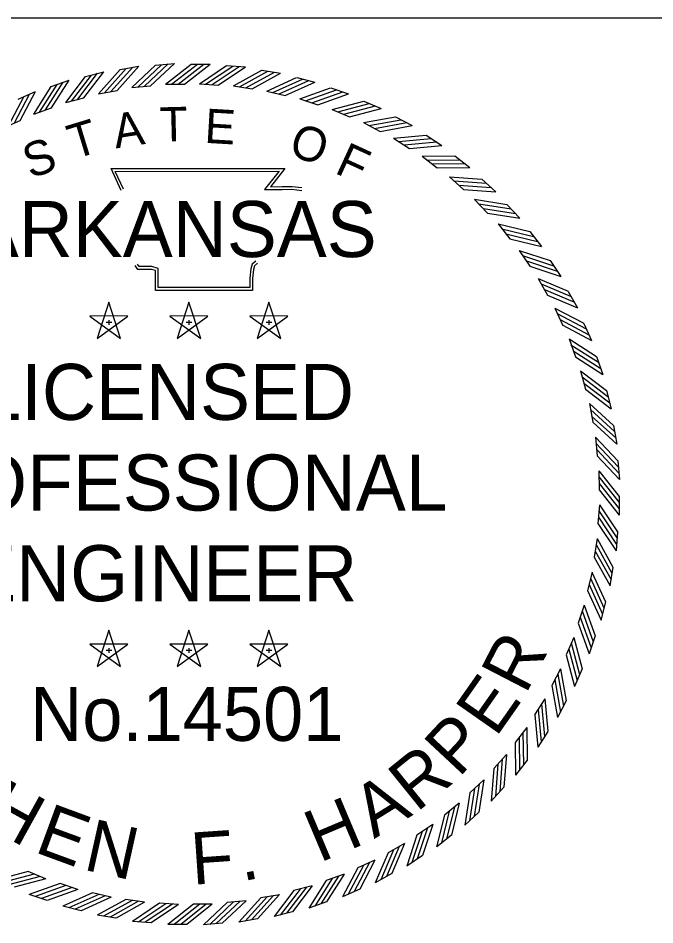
# Model space of a CAD drawing. Extents: x 16 to 1228740, y 11 to 152440.
# Drawn here: x 17.737 to 17.8643, y 10.8174 to 10.9986 of the extents above; entities that cross this region are included whole.
import ezdxf

# ---------------------------------------------------------------- set-up
doc = ezdxf.new("R2010")
doc.units = 0
doc.layers.add('R_No Plot', color=7, linetype='Continuous')
doc.layers.add('STAMP_FRED', color=7, linetype='Continuous')

msp = doc.modelspace()

# ---------------------------------------------------------------- linework, layer by layer
at = {"layer": 'R_No Plot'}
msp.add_line((17.888, 10.99864), (17.47349, 10.99864), dxfattribs=at)
at = {"layer": 'STAMP_FRED'}
for p, q in [((17.75049, 10.98696), (17.75413, 10.98792)), ((17.75745, 10.98838), (17.76116, 10.98904)), ((17.7645, 10.98923), (17.76826, 10.98957)), ((17.77164, 10.98944), (17.77541, 10.98944)), ((17.7787, 10.98916), (17.78246, 10.98888)), ((17.78575, 10.98824), (17.78947, 10.98765)), ((17.74366, 10.98497), (17.74722, 10.98623)), ((17.7927, 10.98675), (17.79636, 10.98586)), ((17.75975, 10.98476), (17.76351, 10.98511)), ((17.7665, 10.98543), (17.77028, 10.98543)), ((17.77328, 10.98553), (17.77705, 10.98526)), ((17.78004, 10.98508), (17.78378, 10.98449)), ((17.7995, 10.98468), (17.80308, 10.98349)), ((17.73703, 10.98242), (17.74047, 10.98397)), ((17.74653, 10.98177), (17.75018, 10.98274)), ((17.75308, 10.98354), (17.7568, 10.9842)), ((17.78675, 10.98407), (17.79042, 10.98317)), ((17.79335, 10.9825), (17.79694, 10.98131)), ((17.74015, 10.97947), (17.74371, 10.98073)), ((17.80611, 10.98207), (17.80957, 10.98058)), ((17.7998, 10.9804), (17.80327, 10.97892)), ((17.81247, 10.97891), (17.81581, 10.97715)), ((17.73398, 10.97665), (17.73743, 10.9782)), ((17.80605, 10.97778), (17.80939, 10.97601)), ((17.81856, 10.97525), (17.82173, 10.97321)), ((17.81206, 10.97464), (17.81525, 10.9726)), ((17.8178, 10.97102), (17.8208, 10.96873)), ((17.82432, 10.97109), (17.82732, 10.9688)), ((17.82321, 10.96694), (17.82602, 10.96441)), ((17.82972, 10.96647), (17.83252, 10.96394)), ((17.82827, 10.96242), (17.83086, 10.95967)), ((17.83472, 10.96142), (17.8373, 10.95867)), ((17.83295, 10.95751), (17.83529, 10.95455)), ((17.83929, 10.95597), (17.84163, 10.95302)), ((17.83719, 10.95222), (17.83929, 10.94908)), ((17.84338, 10.95017), (17.84548, 10.94703)), ((17.84099, 10.9466), (17.84282, 10.9433)), ((17.84699, 10.94404), (17.84882, 10.94074)), ((17.75517, 10.94187), (17.75281, 10.93464)), ((17.75752, 10.93464), (17.75517, 10.94188)), ((17.77116, 10.94187), (17.7688, 10.93464)), ((17.77351, 10.93464), (17.77116, 10.94188)), ((17.78715, 10.94187), (17.78479, 10.93464)), ((17.7895, 10.93464), (17.78715, 10.94188)), ((17.75897, 10.93911), (17.75136, 10.93912)), ((17.75137, 10.93911), (17.75752, 10.93463)), ((17.75282, 10.93464), (17.75898, 10.93911)), ((17.77496, 10.93911), (17.76735, 10.93912)), ((17.76736, 10.93911), (17.77351, 10.93463)), ((17.76881, 10.93464), (17.77497, 10.93911)), ((17.79095, 10.93911), (17.78334, 10.93912)), ((17.78335, 10.93911), (17.7895, 10.93463)), ((17.7848, 10.93464), (17.79096, 10.93911)), ((17.84431, 10.94069), (17.84586, 10.93724)), ((17.75463, 10.9379), (17.75576, 10.9379)), ((17.75518, 10.9383), (17.75518, 10.93735)), ((17.77062, 10.9379), (17.77175, 10.9379)), ((17.77117, 10.9383), (17.77117, 10.93735)), ((17.78661, 10.9379), (17.78774, 10.9379)), ((17.78716, 10.9383), (17.78716, 10.93735)), ((17.85008, 10.93764), (17.85163, 10.9342)), ((17.84713, 10.93452), (17.84839, 10.93096)), ((17.85263, 10.93101), (17.85389, 10.92745)), ((17.84943, 10.92814), (17.85039, 10.92449)), ((17.85462, 10.92419), (17.85558, 10.92054)), ((17.8512, 10.9216), (17.85186, 10.91787)), ((17.85604, 10.91723), (17.8567, 10.91351)), ((17.85242, 10.91492), (17.85277, 10.91116)), ((17.85689, 10.91017), (17.85723, 10.90642)), ((17.85309, 10.90818), (17.85312, 10.9044)), ((17.85714, 10.90307), (17.85718, 10.8993)), ((17.85319, 10.90139), (17.85291, 10.89763)), ((17.85682, 10.89597), (17.85654, 10.89221)), ((17.85274, 10.89463), (17.85215, 10.8909)), ((17.8559, 10.88892), (17.85531, 10.8852)), ((17.85173, 10.88792), (17.85083, 10.88425)), ((17.85016, 10.88132), (17.84897, 10.87774)), ((17.85441, 10.88197), (17.85351, 10.87831)), ((17.75517, 10.87631), (17.75281, 10.86907)), ((17.75752, 10.86908), (17.75517, 10.87632)), ((17.77116, 10.87631), (17.7688, 10.86907)), ((17.77351, 10.86908), (17.77116, 10.87632)), ((17.78715, 10.87631), (17.78479, 10.86907)), ((17.7895, 10.86908), (17.78715, 10.87632)), ((17.84806, 10.87488), (17.84658, 10.8714)), ((17.85234, 10.87517), (17.85115, 10.8716)), ((17.75897, 10.87355), (17.75136, 10.87355)), ((17.75137, 10.87355), (17.75752, 10.86907)), ((17.75282, 10.86908), (17.75898, 10.87355)), ((17.75463, 10.87233), (17.75576, 10.87233)), ((17.75518, 10.87274), (17.75518, 10.87178)), ((17.77496, 10.87355), (17.76735, 10.87355)), ((17.76736, 10.87355), (17.77351, 10.86907)), ((17.76881, 10.86908), (17.77497, 10.87355)), ((17.77062, 10.87233), (17.77175, 10.87233)), ((17.77117, 10.87274), (17.77117, 10.87178)), ((17.79095, 10.87355), (17.78334, 10.87355)), ((17.78335, 10.87355), (17.7895, 10.86907)), ((17.7848, 10.86908), (17.79096, 10.87355)), ((17.78661, 10.87233), (17.78774, 10.87233)), ((17.78716, 10.87274), (17.78716, 10.87178)), ((17.84543, 10.86862), (17.84367, 10.86528)), ((17.84973, 10.86857), (17.84824, 10.8651)), ((17.8423, 10.86261), (17.84026, 10.85943)), ((17.84657, 10.8622), (17.84481, 10.85887)), ((17.83868, 10.85687), (17.83639, 10.85387)), ((17.8429, 10.85611), (17.84087, 10.85294)), ((17.8346, 10.85146), (17.83207, 10.84866)), ((17.83875, 10.85035), (17.83646, 10.84736)), ((17.83008, 10.8464), (17.82733, 10.84381)), ((17.83413, 10.84495), (17.8316, 10.84216)), ((17.82517, 10.84173), (17.82221, 10.83938)), ((17.82908, 10.83995), (17.82633, 10.83737)), ((17.81988, 10.83748), (17.81674, 10.83538)), ((17.82363, 10.83539), (17.82068, 10.83305)), ((17.81426, 10.83368), (17.81096, 10.83185)), ((17.80835, 10.83036), (17.8049, 10.82881)), ((17.81782, 10.83129), (17.81469, 10.8292)), ((17.74253, 10.82661), (17.73906, 10.8281)), ((17.80218, 10.82754), (17.79862, 10.82628)), ((17.8117, 10.82768), (17.8084, 10.82586)), ((17.74898, 10.82451), (17.7454, 10.8257)), ((17.7958, 10.82524), (17.79215, 10.82428)), ((17.74283, 10.82233), (17.73926, 10.82352)), ((17.75558, 10.82295), (17.75191, 10.82384)), ((17.78925, 10.82347), (17.78553, 10.82282)), ((17.8053, 10.82459), (17.80186, 10.82305)), ((17.76229, 10.82194), (17.75856, 10.82252)), ((17.76905, 10.82148), (17.76529, 10.82176)), ((17.77583, 10.82159), (17.77206, 10.82155)), ((17.78258, 10.82225), (17.77882, 10.82191)), ((17.79867, 10.82204), (17.79511, 10.82079)), ((17.74963, 10.82027), (17.74597, 10.82116)), ((17.79185, 10.82005), (17.7882, 10.81909)), ((17.75658, 10.81877), (17.75286, 10.81936)), ((17.76363, 10.81786), (17.75987, 10.81813)), ((17.77783, 10.81779), (17.77408, 10.81744)), ((17.78489, 10.81863), (17.78117, 10.81797)), ((17.77073, 10.81753), (17.76696, 10.81749))]:
    msp.add_line(p, q, dxfattribs=at)
for points in [[(17.75018, 10.98274), (17.75413, 10.98792)], [(17.75307, 10.98354), (17.75744, 10.98838)], [(17.75427, 10.98374), (17.75864, 10.98858)], [(17.75556, 10.98399), (17.75992, 10.98884)], [(17.75679, 10.9842), (17.76116, 10.98904)], [(17.75974, 10.98476), (17.7645, 10.98922)], [(17.76095, 10.98486), (17.76571, 10.98932)], [(17.76226, 10.98501), (17.76701, 10.98947)], [(17.76351, 10.98511), (17.76826, 10.98958)], [(17.76649, 10.98542), (17.77164, 10.98943)], [(17.76771, 10.98541), (17.77285, 10.98942)], [(17.76902, 10.98544), (17.77416, 10.98945)], [(17.77027, 10.98543), (17.77542, 10.98944)], [(17.77327, 10.98553), (17.7787, 10.98915)], [(17.77448, 10.98543), (17.77991, 10.98905)], [(17.77579, 10.98536), (17.78122, 10.98898)], [(17.77704, 10.98526), (17.78247, 10.98888)], [(17.78004, 10.98508), (17.78574, 10.98824)], [(17.78124, 10.98488), (17.78694, 10.98804)], [(17.74371, 10.98073), (17.74722, 10.98623)], [(17.74653, 10.98177), (17.75048, 10.98696)], [(17.7477, 10.98207), (17.75166, 10.98726)], [(17.74896, 10.98243), (17.75292, 10.98762)], [(17.78253, 10.9847), (17.78824, 10.98786)], [(17.78377, 10.98449), (17.78948, 10.98766)], [(17.78675, 10.98406), (17.79269, 10.98674)], [(17.78792, 10.98377), (17.79387, 10.98645)], [(17.7892, 10.98348), (17.79515, 10.98617)], [(17.74015, 10.97947), (17.74366, 10.98496)], [(17.7413, 10.97986), (17.74481, 10.98536)], [(17.74252, 10.98033), (17.74603, 10.98582)], [(17.79042, 10.98318), (17.79636, 10.98586)], [(17.79334, 10.9825), (17.79949, 10.98468)], [(17.79449, 10.98211), (17.80064, 10.98429)], [(17.73509, 10.97713), (17.73814, 10.9829)], [(17.73628, 10.9777), (17.73932, 10.98347)], [(17.73743, 10.9782), (17.74047, 10.98397)], [(17.79574, 10.98172), (17.80189, 10.9839)], [(17.79693, 10.98131), (17.80308, 10.98349)], [(17.79979, 10.9804), (17.8061, 10.98207)], [(17.8009, 10.97991), (17.80721, 10.98158)], [(17.80212, 10.97942), (17.80843, 10.98109)], [(17.80327, 10.97892), (17.80958, 10.98059)], [(17.80604, 10.97777), (17.81247, 10.97891)], [(17.80711, 10.9772), (17.81353, 10.97834)], [(17.80828, 10.97661), (17.81471, 10.97775)], [(17.80939, 10.97601), (17.81581, 10.97715)], [(17.81206, 10.97464), (17.81855, 10.97525)], [(17.81307, 10.97398), (17.81957, 10.97458)], [(17.81419, 10.97329), (17.82069, 10.9739)], [(17.81524, 10.97261), (17.82174, 10.97321)], [(17.81779, 10.97102), (17.82432, 10.97109)], [(17.81875, 10.97028), (17.82527, 10.97034)], [(17.7576, 10.96421), (17.75559, 10.96856), (17.79036, 10.96858), (17.78745, 10.96493), (17.78981, 10.96496), (17.79179, 10.96499), (17.79376, 10.96477)], [(17.7581, 10.96444), (17.75645, 10.96801), (17.78921, 10.96803), (17.7863, 10.96436), (17.78982, 10.96441), (17.79176, 10.96443), (17.7937, 10.96422)], [(17.81981, 10.9695), (17.82633, 10.96957)], [(17.8208, 10.96873), (17.82732, 10.9688)], [(17.82321, 10.96694), (17.82971, 10.96647)], [(17.8241, 10.96612), (17.83061, 10.96565)], [(17.82509, 10.96526), (17.8316, 10.96479)], [(17.82602, 10.96441), (17.83252, 10.96394)], [(17.82827, 10.96243), (17.83471, 10.96142)], [(17.82909, 10.96153), (17.83554, 10.96052)], [(17.83001, 10.9606), (17.83645, 10.95959)], [(17.83086, 10.95967), (17.8373, 10.95867)], [(17.83294, 10.95751), (17.83928, 10.95597)], [(17.83368, 10.95655), (17.84002, 10.95501)], [(17.83452, 10.95554), (17.84086, 10.95401)], [(17.83529, 10.95455), (17.84163, 10.95302)], [(17.83719, 10.95222), (17.84338, 10.95017)], [(17.78453, 10.95006), (17.7838, 10.94947), (17.78354, 10.94854), (17.78334, 10.94666), (17.78334, 10.94478), (17.76503, 10.94478), (17.76503, 10.94747), (17.76503, 10.9486), (17.76378, 10.94898), (17.76123, 10.94898), (17.7609, 10.94948)], [(17.83785, 10.95121), (17.84404, 10.94915)], [(17.8386, 10.95013), (17.84479, 10.94808)], [(17.78488, 10.94964), (17.78428, 10.94915), (17.78409, 10.94843), (17.78389, 10.94663), (17.78389, 10.94423), (17.76448, 10.94423), (17.76448, 10.94747), (17.76448, 10.94819), (17.76369, 10.94843), (17.76093, 10.94843), (17.76044, 10.94918)], [(17.83929, 10.94908), (17.84548, 10.94703)], [(17.84099, 10.9466), (17.84699, 10.94405)], [(17.84156, 10.94554), (17.84756, 10.94298)], [(17.84222, 10.94441), (17.84822, 10.94185)], [(17.84282, 10.9433), (17.84882, 10.94074)], [(17.84431, 10.94069), (17.85007, 10.93765)], [(17.84479, 10.93958), (17.85056, 10.93653)], [(17.84536, 10.9384), (17.85112, 10.93535)], [(17.84586, 10.93725), (17.85163, 10.9342)], [(17.84713, 10.93452), (17.85262, 10.93101)], [(17.84752, 10.93338), (17.85302, 10.92987)], [(17.84798, 10.93215), (17.85348, 10.92864)], [(17.84839, 10.93096), (17.85389, 10.92745)], [(17.84943, 10.92815), (17.85462, 10.92419)], [(17.84973, 10.92697), (17.85491, 10.92302)], [(17.85009, 10.92571), (17.85528, 10.92176)], [(17.8504, 10.92449), (17.85558, 10.92054)], [(17.8512, 10.9216), (17.85604, 10.91723)], [(17.8514, 10.9204), (17.85624, 10.91603)], [(17.85165, 10.91912), (17.8565, 10.91475)], [(17.85186, 10.91788), (17.8567, 10.91351)], [(17.85242, 10.91493), (17.85688, 10.91017)], [(17.85252, 10.91372), (17.85698, 10.90897)], [(17.85267, 10.91242), (17.85713, 10.90766)], [(17.85277, 10.91117), (17.85724, 10.90641)], [(17.85308, 10.90818), (17.85714, 10.90307)], [(17.85308, 10.90697), (17.85714, 10.90186)], [(17.85312, 10.90566), (17.85718, 10.90055)], [(17.85312, 10.9044), (17.85718, 10.89929)], [(17.85319, 10.9014), (17.85681, 10.89598)], [(17.85309, 10.90019), (17.85671, 10.89477)], [(17.85292, 10.89763), (17.85654, 10.89221)], [(17.85302, 10.89888), (17.85664, 10.89346)], [(17.85273, 10.89463), (17.8559, 10.88893)], [(17.85236, 10.89214), (17.85552, 10.88643)], [(17.85253, 10.89344), (17.8557, 10.88773)], [(17.85215, 10.8909), (17.85532, 10.88519)], [(17.85143, 10.88675), (17.85411, 10.8808)], [(17.85172, 10.88793), (17.8544, 10.88198)], [(17.85114, 10.88547), (17.85382, 10.87953)], [(17.85084, 10.88425), (17.85352, 10.87831)], [(17.85016, 10.88133), (17.85234, 10.87518)], [(17.84977, 10.88018), (17.85195, 10.87403)], [(17.84897, 10.87774), (17.85115, 10.87159)], [(17.84938, 10.87893), (17.85156, 10.87278)], [(17.84757, 10.87377), (17.84924, 10.86746)], [(17.84806, 10.87488), (17.84973, 10.86857)], [(17.84708, 10.87255), (17.84875, 10.86625)], [(17.84658, 10.8714), (17.84825, 10.8651)], [(17.84543, 10.86863), (17.84657, 10.86221)], [(17.84486, 10.86756), (17.846, 10.86114)], [(17.84367, 10.86529), (17.84481, 10.85886)], [(17.84427, 10.86639), (17.84541, 10.85997)], [(17.84164, 10.8616), (17.84224, 10.8551)], [(17.8423, 10.86261), (17.8429, 10.85612)], [(17.84027, 10.85943), (17.84087, 10.85293)], [(17.84095, 10.86048), (17.84156, 10.85399)], [(17.83793, 10.85592), (17.838, 10.8494)], [(17.83868, 10.85688), (17.83875, 10.85036)], [(17.83639, 10.85387), (17.83646, 10.84735)], [(17.83716, 10.85486), (17.83723, 10.84834)], [(17.83378, 10.85057), (17.8333, 10.84407)], [(17.8346, 10.85146), (17.83413, 10.84496)], [(17.83207, 10.84866), (17.8316, 10.84215)], [(17.83292, 10.84958), (17.83245, 10.84307)], [(17.82919, 10.84558), (17.82818, 10.83914)], [(17.83008, 10.8464), (17.82908, 10.83996)], [(17.82733, 10.84381), (17.82632, 10.83737)], [(17.82826, 10.84467), (17.82725, 10.83822)], [(17.82517, 10.84173), (17.82363, 10.83539)], [(17.82221, 10.83938), (17.82067, 10.83304)], [(17.8232, 10.84015), (17.82167, 10.83381)], [(17.82421, 10.84099), (17.82267, 10.83465)], [(17.81779, 10.83607), (17.81574, 10.82988)], [(17.81887, 10.83682), (17.81681, 10.83063)], [(17.81988, 10.83749), (17.81783, 10.83129)], [(17.81674, 10.83538), (17.81469, 10.82919)], [(17.81207, 10.83245), (17.80951, 10.82645)], [(17.8132, 10.83311), (17.81064, 10.82711)], [(17.81426, 10.83369), (17.8117, 10.82769)], [(17.80835, 10.83037), (17.80531, 10.8246)], [(17.81096, 10.83185), (17.8084, 10.82585)], [(17.80491, 10.82881), (17.80186, 10.82304)], [(17.80606, 10.82932), (17.80301, 10.82355)], [(17.80724, 10.82988), (17.80419, 10.82411)], [(17.73906, 10.82809), (17.73276, 10.82643)], [(17.74021, 10.82759), (17.73391, 10.82592)], [(17.74143, 10.8271), (17.73512, 10.82543)], [(17.79981, 10.82669), (17.7963, 10.82119)], [(17.80104, 10.82715), (17.79752, 10.82166)], [(17.80218, 10.82755), (17.79867, 10.82205)], [(17.74254, 10.82661), (17.73623, 10.82495)], [(17.7454, 10.8257), (17.73925, 10.82352)], [(17.74659, 10.82529), (17.74044, 10.82311)], [(17.74784, 10.82491), (17.74169, 10.82272)], [(17.79463, 10.82495), (17.79068, 10.81976)], [(17.79581, 10.82524), (17.79185, 10.82006)], [(17.79862, 10.82628), (17.79511, 10.82078)], [(17.74899, 10.82451), (17.74284, 10.82233)], [(17.75191, 10.82384), (17.74597, 10.82116)], [(17.75313, 10.82353), (17.74719, 10.82085)], [(17.75441, 10.82325), (17.74846, 10.82057)], [(17.78678, 10.82302), (17.78241, 10.81818)], [(17.78806, 10.82328), (17.78369, 10.81843)], [(17.78926, 10.82348), (17.78489, 10.81863)], [(17.79215, 10.82428), (17.7882, 10.81909)], [(17.79337, 10.82459), (17.78942, 10.8194)], [(17.75559, 10.82295), (17.74964, 10.82027)], [(17.75856, 10.82252), (17.75285, 10.81936)], [(17.7598, 10.82231), (17.75409, 10.81915)], [(17.7611, 10.82214), (17.75539, 10.81898)], [(17.76229, 10.82194), (17.75659, 10.81878)], [(17.76529, 10.82176), (17.75987, 10.81813)], [(17.76654, 10.82165), (17.76112, 10.81803)], [(17.76785, 10.82158), (17.76243, 10.81796)], [(17.76906, 10.82148), (17.76363, 10.81786)], [(17.77206, 10.82155), (17.76695, 10.81749)], [(17.77332, 10.82155), (17.76821, 10.81749)], [(17.77463, 10.82159), (17.76952, 10.81753)], [(17.77584, 10.82159), (17.77073, 10.81753)], [(17.77883, 10.8219), (17.77407, 10.81744)], [(17.78008, 10.82201), (17.77532, 10.81754)], [(17.78138, 10.82216), (17.77662, 10.81769)], [(17.78259, 10.82226), (17.77783, 10.81779)], [(17.78554, 10.82281), (17.78117, 10.81797)]]:
    msp.add_lwpolyline(points, dxfattribs=at)

# ---------------------------------------------------------------- texts
for s, height, rotation, p in [('T', 0.00686, 1.4789, (17.76539, 10.97394)), ('A', 0.00686, 8.6788, (17.75654, 10.97258)), ('E', 0.00686, 356.672, (17.77417, 10.97373)), ('T', 0.00686, 16.9015, (17.74821, 10.9704)), ('O', 0.00686, 341.2218, (17.79082, 10.97138)), ('S', 0.00686, 19.7726, (17.73949, 10.96649)), ('F', 0.00686, 335.3628, (17.80007, 10.96777)), ('R', 0.01042, 62.6418, (17.83844, 10.86329)), ('E', 0.01042, 54.981, (17.83249, 10.85473)), ('P', 0.01042, 46.9554, (17.82508, 10.8467)), ('R', 0.01042, 38.9298, (17.81663, 10.83978)), ('H', 0.01042, 331.0769, (17.72951, 10.83771)), ('A', 0.01042, 31.6338, (17.80817, 10.83457)), ('E', 0.01042, 339.8321, (17.74002, 10.83208)), ('H', 0.01042, 22.8786, (17.79725, 10.82979)), ('N', 0.01042, 347.4929, (17.74982, 10.82852)), ('F', 0.01042, 3.9089, (17.77189, 10.82544)), ('.', 0.01042, 11.205, (17.7818, 10.82611))]:
    msp.add_text(s, height=height, rotation=rotation, dxfattribs=at).set_placement(p)
for s, height, p in [('ARKANSAS', 0.011193, (17.72717, 10.95089)), ('LICENSED', 0.011193, (17.7293, 10.91835)), ('PROFESSIONAL', 0.0111934, (17.70638, 10.90023)), ('ENGINEER', 0.011193, (17.72663, 10.88211)), ('No.14501', 0.010794, (17.73943, 10.8542))]:
    msp.add_text(s, height=height, dxfattribs=at).set_placement(p)

doc.saveas('drawing.dxf')
